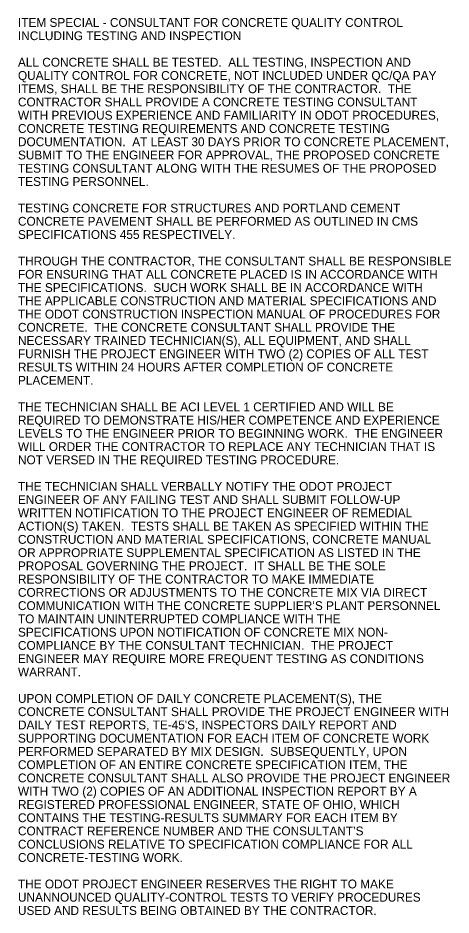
# Model space of a CAD drawing. Extents: x -9.6 to 49.4, y 0 to 27.9.
# Drawn here: x 42.58 to 49.43, y 1.83 to 16.05 of the extents above; entities that cross this region are included whole.
import ezdxf

# ---------------------------------------------------------------- set-up
doc = ezdxf.new("R2010")
doc.units = 0
doc.layers.add('SH_Text', color=7, linetype='Continuous')

msp = doc.modelspace()

# ---------------------------------------------------------------- texts
at = {"layer": 'SH_Text'}
for s, p in [('ITEM SPECIAL - CONSULTANT FOR CONCRETE QUALITY CONTROL ', (42.577, 15.905)), ('INCLUDING TESTING AND INSPECTION', (42.577, 15.695)), ('ALL CONCRETE SHALL BE TESTED.  ALL TESTING, INSPECTION AND ', (42.577, 15.275)), ('QUALITY CONTROL FOR CONCRETE, NOT INCLUDED UNDER QC/QA PAY ', (42.577, 15.065)), ('ITEMS, SHALL BE THE RESPONSIBILITY OF THE CONTRACTOR.  THE ', (42.577, 14.855)), ('CONTRACTOR SHALL PROVIDE A CONCRETE TESTING CONSULTANT ', (42.577, 14.645)), ('WITH PREVIOUS EXPERIENCE AND FAMILIARITY IN ODOT PROCEDURES, ', (42.577, 14.435)), ('CONCRETE TESTING REQUIREMENTS AND CONCRETE TESTING ', (42.577, 14.225)), ('DOCUMENTATION.  AT LEAST 30 DAYS PRIOR TO CONCRETE PLACEMENT, ', (42.577, 14.015)), ('SUBMIT TO THE ENGINEER FOR APPROVAL, THE PROPOSED CONCRETE ', (42.577, 13.805)), ('TESTING CONSULTANT ALONG WITH THE RESUMES OF THE PROPOSED ', (42.577, 13.595)), ('TESTING PERSONNEL.  ', (42.577, 13.385)), ('TESTING CONCRETE FOR STRUCTURES AND PORTLAND CEMENT ', (42.577, 12.965)), ('CONCRETE PAVEMENT SHALL BE PERFORMED AS OUTLINED IN CMS ', (42.577, 12.755)), ('SPECIFICATIONS 455 RESPECTIVELY.', (42.577, 12.545)), ('THROUGH THE CONTRACTOR, THE CONSULTANT SHALL BE RESPONSIBLE ', (42.577, 12.125)), ('FOR ENSURING THAT ALL CONCRETE PLACED IS IN ACCORDANCE WITH ', (42.577, 11.915)), ('THE SPECIFICATIONS.  SUCH WORK SHALL BE IN ACCORDANCE WITH ', (42.577, 11.705)), ('THE APPLICABLE CONSTRUCTION AND MATERIAL SPECIFICATIONS AND ', (42.577, 11.495)), ('THE ODOT CONSTRUCTION INSPECTION MANUAL OF PROCEDURES FOR ', (42.577, 11.285)), ('CONCRETE.  THE CONCRETE CONSULTANT SHALL PROVIDE THE ', (42.577, 11.075)), ('NECESSARY TRAINED TECHNICIAN(S), ALL EQUIPMENT, AND SHALL ', (42.577, 10.865)), ('FURNISH THE PROJECT ENGINEER WITH TWO (2) COPIES OF ALL TEST ', (42.577, 10.655)), ('RESULTS WITHIN 24 HOURS AFTER COMPLETION OF CONCRETE ', (42.577, 10.445)), ('PLACEMENT.', (42.577, 10.235)), ('THE TECHNICIAN SHALL BE ACI LEVEL 1 CERTIFIED AND WILL BE ', (42.577, 9.815)), ('REQUIRED TO DEMONSTRATE HIS/HER COMPETENCE AND EXPERIENCE ', (42.577, 9.605)), ('LEVELS TO THE ENGINEER PRIOR TO BEGINNING WORK.  THE ENGINEER ', (42.577, 9.395)), ('WILL ORDER THE CONTRACTOR TO REPLACE ANY TECHNICIAN THAT IS ', (42.577, 9.185)), ('NOT VERSED IN THE REQUIRED TESTING PROCEDURE.', (42.577, 8.975)), ('THE TECHNICIAN SHALL VERBALLY NOTIFY THE ODOT PROJECT ', (42.577, 8.555)), ('ENGINEER OF ANY FAILING TEST AND SHALL SUBMIT FOLLOW-UP ', (42.577, 8.345)), ('WRITTEN NOTIFICATION TO THE PROJECT ENGINEER OF REMEDIAL ', (42.577, 8.135)), ('ACTION(S) TAKEN.  TESTS SHALL BE TAKEN AS SPECIFIED WITHIN THE ', (42.577, 7.925)), ('CONSTRUCTION AND MATERIAL SPECIFICATIONS, CONCRETE MANUAL ', (42.577, 7.715)), ('OR APPROPRIATE SUPPLEMENTAL SPECIFICATION AS LISTED IN THE ', (42.577, 7.505)), ('PROPOSAL GOVERNING THE PROJECT.  IT SHALL BE THE SOLE ', (42.577, 7.295)), ('RESPONSIBILITY OF THE CONTRACTOR TO MAKE IMMEDIATE ', (42.577, 7.085)), ('CORRECTIONS OR ADJUSTMENTS TO THE CONCRETE MIX VIA DIRECT ', (42.577, 6.875)), ('COMMUNICATION WITH THE CONCRETE SUPPLIER’S PLANT PERSONNEL ', (42.577, 6.665)), ('TO MAINTAIN UNINTERRUPTED COMPLIANCE WITH THE ', (42.577, 6.455)), ('SPECIFICATIONS UPON NOTIFICATION OF CONCRETE MIX NON-', (42.577, 6.245)), ('COMPLIANCE BY THE CONSULTANT TECHNICIAN.  THE PROJECT ', (42.577, 6.035)), ('ENGINEER MAY REQUIRE MORE FREQUENT TESTING AS CONDITIONS ', (42.577, 5.825)), ('WARRANT.', (42.577, 5.615)), ('UPON COMPLETION OF DAILY CONCRETE PLACEMENT(S), THE ', (42.577, 5.195)), ('CONCRETE CONSULTANT SHALL PROVIDE THE PROJECT ENGINEER WITH ', (42.577, 4.985)), ("DAILY TEST REPORTS, TE-45'S, INSPECTORS DAILY REPORT AND ", (42.577, 4.775)), ('SUPPORTING DOCUMENTATION FOR EACH ITEM OF CONCRETE WORK ', (42.577, 4.565)), ('PERFORMED SEPARATED BY MIX DESIGN.  SUBSEQUENTLY, UPON ', (42.577, 4.355)), ('COMPLETION OF AN ENTIRE CONCRETE SPECIFICATION ITEM, THE ', (42.577, 4.145)), ('CONCRETE CONSULTANT SHALL ALSO PROVIDE THE PROJECT ENGINEER ', (42.577, 3.935)), ('WITH TWO (2) COPIES OF AN ADDITIONAL INSPECTION REPORT BY A ', (42.577, 3.725)), ('REGISTERED PROFESSIONAL ENGINEER, STATE OF OHIO, WHICH ', (42.577, 3.515)), ('CONTAINS THE TESTING-RESULTS SUMMARY FOR EACH ITEM BY ', (42.577, 3.305)), ('CONTRACT REFERENCE NUMBER AND THE CONSULTANT’S ', (42.577, 3.095)), ('CONCLUSIONS RELATIVE TO SPECIFICATION COMPLIANCE FOR ALL ', (42.577, 2.885)), ('CONCRETE-TESTING WORK.', (42.577, 2.675)), ('THE ODOT PROJECT ENGINEER RESERVES THE RIGHT TO MAKE ', (42.577, 2.255)), ('UNANNOUNCED QUALITY-CONTROL TESTS TO VERIFY PROCEDURES ', (42.577, 2.045)), ('USED AND RESULTS BEING OBTAINED BY THE CONTRACTOR.', (42.577, 1.835))]:
    msp.add_text(s, height=0.14, dxfattribs=at).set_placement(p)

doc.saveas('drawing.dxf')
